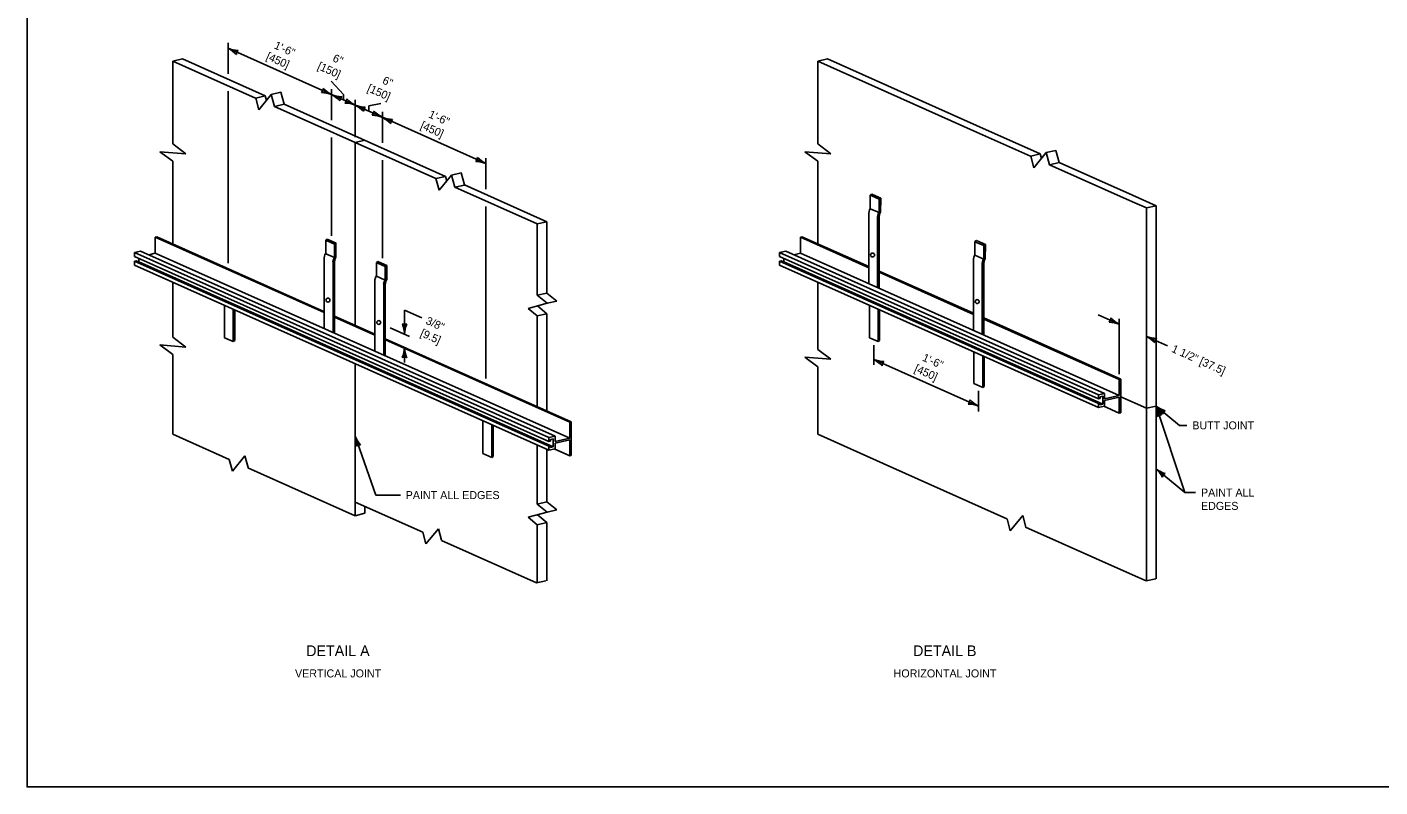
# Model space of a CAD drawing. Extents: x 49991.4 to 50021, y 49987.6 to 50011.4.
# Drawn here: x 49999.38 to 50009.53, y 49987.8 to 49993.5 of the extents above; entities that cross this region are included whole.
import ezdxf

# ---------------------------------------------------------------- set-up
doc = ezdxf.new("R2010")
doc.units = 0
for name, color, linetype in [('Level 1', 7, 'Continuous'), ('Level 2', 7, 'Continuous'), ('Level 3', 7, 'Continuous'), ('Level 6', 7, 'Continuous')]:
    doc.layers.add(name, color=color, linetype=linetype)

msp = doc.modelspace()

# ---------------------------------------------------------------- linework, layer by layer
at = {"layer": 'Level 1'}
for p, q in [((50001.844, 49991.263), (50001.844, 49992.63)), ((50005.718, 49992.243), (50005.707, 49992.236)), ((50005.707, 49992.134), (50005.707, 49992.236)), ((50005.718, 49992.231), (50005.707, 49992.236)), ((50005.785, 49992.213), (50005.718, 49992.243)), ((50005.774, 49992.206), (50005.718, 49992.231)), ((50005.773, 49992.105), (50005.774, 49992.206)), ((50005.785, 49992.213), (50005.774, 49992.206)), ((50005.784, 49992.106), (50005.785, 49992.213)), ((50007.85, 49989.36), (50007.85, 49992.157)), ((50005.695, 49991.572), (50005.696, 49992.102)), ((50005.773, 49992.105), (50005.707, 49992.134)), ((50005.762, 49991.543), (50005.762, 49992.073)), ((50005.773, 49991.538), (50005.773, 49992.074)), ((50007.778, 49989.343), (50007.778, 49992.14)), ((50000.345, 49991.92), (50000.357, 49991.923)), ((50000.345, 49991.8), (50000.345, 49991.92)), ((50001.611, 49991.355), (50000.345, 49991.92)), ((50001.61, 49991.364), (50000.357, 49991.923)), ((50001.634, 49991.906), (50001.623, 49991.898)), ((50001.623, 49991.797), (50001.623, 49991.898)), ((50001.634, 49991.893), (50001.623, 49991.898)), ((50001.701, 49991.876), (50001.634, 49991.906)), ((50001.689, 49991.868), (50001.634, 49991.893)), ((50001.701, 49991.876), (50001.689, 49991.868)), ((50001.689, 49991.768), (50001.689, 49991.868)), ((50001.7, 49991.768), (50001.7, 49991.876)), ((50005.183, 49991.921), (50005.194, 49991.924)), ((50005.183, 49991.801), (50005.183, 49991.921)), ((50005.695, 49991.692), (50005.183, 49991.921)), ((50005.695, 49991.7), (50005.194, 49991.924)), ((50006.503, 49991.895), (50006.492, 49991.888)), ((50006.492, 49991.786), (50006.492, 49991.888)), ((50006.503, 49991.882), (50006.492, 49991.888)), ((50006.57, 49991.865), (50006.503, 49991.895)), ((50006.559, 49991.858), (50006.503, 49991.882)), ((50006.558, 49991.757), (50006.559, 49991.858)), ((50006.57, 49991.865), (50006.559, 49991.858)), ((50006.569, 49991.757), (50006.57, 49991.865)), ((50000.189, 49991.806), (50000.235, 49991.817)), ((50000.189, 49991.806), (50000.189, 49991.776)), ((50003.297, 49990.419), (50000.189, 49991.806)), ((50003.297, 49990.389), (50000.189, 49991.776)), ((50000.221, 49991.736), (50000.221, 49991.762)), ((50003.343, 49990.43), (50000.235, 49991.817)), ((50000.345, 49991.8), (50000.297, 49991.789)), ((50003.453, 49990.414), (50000.345, 49991.8)), ((50001.611, 49991.236), (50001.611, 49991.765)), ((50001.689, 49991.768), (50001.623, 49991.797)), ((50005.027, 49991.806), (50005.073, 49991.817)), ((50007.418, 49990.739), (50005.027, 49991.806)), ((50005.027, 49991.806), (50005.027, 49991.777)), ((50007.418, 49990.709), (50005.027, 49991.776)), ((50005.059, 49991.737), (50005.059, 49991.762)), ((50007.464, 49990.75), (50005.073, 49991.817)), ((50005.183, 49991.801), (50005.135, 49991.789)), ((50007.574, 49990.734), (50005.183, 49991.801)), ((50006.48, 49991.222), (50006.481, 49991.754)), ((50006.558, 49991.757), (50006.492, 49991.786)), ((50000.189, 49991.741), (50000.201, 49991.743)), ((50003.297, 49990.354), (50000.189, 49991.741)), ((50000.189, 49991.741), (50000.189, 49991.711)), ((50003.297, 49990.324), (50000.189, 49991.711)), ((50003.308, 49990.356), (50000.201, 49991.743)), ((50000.221, 49991.736), (50000.219, 49991.735)), ((50003.328, 49990.35), (50000.221, 49991.736)), ((50001.678, 49991.206), (50001.678, 49991.735)), ((50001.689, 49991.201), (50001.689, 49991.736)), ((50002.015, 49991.738), (50002.003, 49991.73)), ((50002.003, 49991.628), (50002.003, 49991.73)), ((50002.015, 49991.725), (50002.003, 49991.73)), ((50002.081, 49991.708), (50002.015, 49991.738)), ((50002.07, 49991.7), (50002.015, 49991.725)), ((50002.069, 49991.599), (50002.07, 49991.7)), ((50002.081, 49991.708), (50002.07, 49991.7)), ((50002.081, 49991.6), (50002.081, 49991.708)), ((50005.027, 49991.741), (50005.039, 49991.744)), ((50007.418, 49990.674), (50005.027, 49991.741)), ((50005.027, 49991.741), (50005.027, 49991.711)), ((50007.418, 49990.644), (50005.027, 49991.711)), ((50007.43, 49990.676), (50005.039, 49991.744)), ((50005.056, 49991.736), (50005.059, 49991.737)), ((50007.45, 49990.67), (50005.059, 49991.737)), ((50006.48, 49991.35), (50005.773, 49991.665)), ((50006.48, 49991.342), (50005.773, 49991.658)), ((50006.547, 49991.192), (50006.547, 49991.725)), ((50006.558, 49991.187), (50006.558, 49991.725)), ((50001.992, 49991.066), (50001.992, 49991.596)), ((50002.069, 49991.599), (50002.003, 49991.628)), ((50002.058, 49991.036), (50002.058, 49991.567)), ((50002.069, 49991.031), (50002.069, 49991.568)), ((50000.863, 49991.41), (50000.863, 49991.167)), ((50000.929, 49991.38), (50000.929, 49991.138)), ((50000.941, 49991.375), (50000.941, 49991.145)), ((50005.7, 49991.411), (50005.7, 49991.167)), ((50005.766, 49991.381), (50005.766, 49991.138)), ((50005.777, 49991.376), (50005.777, 49991.145)), ((50001.991, 49991.194), (50001.689, 49991.329)), ((50001.992, 49991.185), (50001.689, 49991.321)), ((50007.586, 49990.856), (50006.558, 49991.315)), ((50007.574, 49990.853), (50006.558, 49991.307)), ((50000.929, 49991.138), (50000.863, 49991.167)), ((50000.941, 49991.145), (50000.929, 49991.138)), ((50003.464, 49990.536), (50002.07, 49991.158)), ((50003.453, 49990.533), (50002.071, 49991.15)), ((50005.766, 49991.138), (50005.7, 49991.167)), ((50005.777, 49991.145), (50005.766, 49991.138)), ((50006.484, 49991.061), (50006.484, 49990.823)), ((50001.844, 49989.832), (50001.844, 49990.972)), ((50006.551, 49991.031), (50006.551, 49990.794)), ((50006.562, 49991.026), (50006.562, 49990.801)), ((50007.574, 49990.853), (50007.586, 49990.856)), ((50007.574, 49990.734), (50007.574, 49990.853)), ((50007.586, 49990.699), (50007.586, 49990.856)), ((50007.586, 49990.604), (50007.586, 49990.856)), ((50006.551, 49990.794), (50006.484, 49990.823)), ((50006.562, 49990.801), (50006.551, 49990.794)), ((50007.418, 49990.739), (50007.464, 49990.75)), ((50007.418, 49990.739), (50007.418, 49990.709)), ((50007.464, 49990.708), (50007.464, 49990.75)), ((50007.418, 49990.709), (50007.43, 49990.712)), ((50007.418, 49990.674), (50007.43, 49990.676)), ((50007.418, 49990.674), (50007.418, 49990.644)), ((50007.418, 49990.644), (50007.464, 49990.655)), ((50007.43, 49990.724), (50007.45, 49990.728)), ((50007.43, 49990.724), (50007.43, 49990.712)), ((50007.43, 49990.676), (50007.43, 49990.665)), ((50007.43, 49990.665), (50007.45, 49990.67)), ((50007.45, 49990.67), (50007.45, 49990.728)), ((50007.574, 49990.602), (50007.459, 49990.653)), ((50007.574, 49990.734), (50007.464, 49990.708)), ((50007.574, 49990.722), (50007.464, 49990.696)), ((50007.464, 49990.655), (50007.464, 49990.696)), ((50007.574, 49990.602), (50007.574, 49990.722)), ((50007.778, 49990.638), (50007.586, 49990.723)), ((50007.778, 49990.638), (50007.85, 49990.654)), ((50002.801, 49990.545), (50002.801, 49990.298)), ((50003.45, 49990.533), (50003.465, 49990.536)), ((50003.453, 49990.533), (50003.464, 49990.536)), ((50003.453, 49990.414), (50003.453, 49990.533)), ((50003.464, 49990.284), (50003.464, 49990.536)), ((50007.574, 49990.602), (50007.586, 49990.604)), ((50002.868, 49990.515), (50002.868, 49990.269)), ((50002.879, 49990.51), (50002.879, 49990.276)), ((50003.297, 49990.419), (50003.343, 49990.43)), ((50003.297, 49990.419), (50003.297, 49990.389)), ((50003.297, 49990.389), (50003.308, 49990.392)), ((50003.297, 49990.354), (50003.308, 49990.356)), ((50003.297, 49990.354), (50003.297, 49990.324)), ((50003.297, 49990.324), (50003.343, 49990.335)), ((50003.308, 49990.403), (50003.328, 49990.408)), ((50003.308, 49990.403), (50003.308, 49990.392)), ((50003.308, 49990.356), (50003.308, 49990.345)), ((50003.308, 49990.345), (50003.328, 49990.35)), ((50003.328, 49990.35), (50003.328, 49990.408)), ((50003.453, 49990.282), (50003.337, 49990.333)), ((50003.343, 49990.388), (50003.343, 49990.43)), ((50003.453, 49990.414), (50003.343, 49990.388)), ((50003.453, 49990.402), (50003.343, 49990.376)), ((50003.343, 49990.335), (50003.343, 49990.376)), ((50003.453, 49990.282), (50003.453, 49990.402)), ((50002.868, 49990.269), (50002.801, 49990.298)), ((50002.879, 49990.276), (50002.868, 49990.269)), ((50003.453, 49990.282), (50003.464, 49990.284)), ((50001.916, 49989.851), (50001.916, 49989.903))]:
    msp.add_line(p, q, dxfattribs=at)
msp.add_lwpolyline([(49999.384, 49998.999), (50016.75, 49998.999), (50016.75, 49987.799), (49999.384, 49987.799)], close=True, dxfattribs=at)
for centre in [(50005.724, 49991.787), (50001.64, 49991.449), (50006.509, 49991.438), (50002.021, 49991.281)]:
    msp.add_circle(centre, 0.0147, dxfattribs=at)
for centre, start_param, end_param in [((50005.702, 49992.101), 0.015278, 1.570796), ((50005.768, 49992.072), 6.267677, 7.853982), ((50005.779, 49992.073), 6.255637, 7.853982), ((50001.618, 49991.764), 0, 1.570796), ((50001.684, 49991.734), 0, 1.570796), ((50001.695, 49991.735), 0, 1.570796), ((50006.487, 49991.753), 6.276621, 7.853982), ((50006.553, 49991.724), 6.261574, 7.853982), ((50006.564, 49991.724), 6.249472, 7.853982), ((50001.998, 49991.595), 6.271013, 7.853982), ((50002.064, 49991.566), 6.256054, 7.853982), ((50002.076, 49991.567), 6.24387, 7.853982)]:
    msp.add_ellipse(centre, major_axis=(0.0049, 0.033), ratio=0.190283, start_param=start_param, end_param=end_param, dxfattribs=at)
at = {"layer": 'Level 3'}
for p, q in [((50000.891, 49993.145), (50000.891, 49993.377)), ((50001.667, 49992.99), (50000.891, 49993.337)), ((50001.756, 49992.99), (50001.664, 49993.091)), ((50000.891, 49991.725), (50000.891, 49993.016)), ((50001.667, 49992.798), (50001.667, 49993.03)), ((50001.844, 49992.911), (50001.667, 49992.99)), ((50001.756, 49992.95), (50001.756, 49992.99)), ((50001.844, 49992.67), (50001.844, 49992.951)), ((50002.048, 49992.82), (50001.844, 49992.911)), ((50001.946, 49992.905), (50002.037, 49992.924)), ((50001.946, 49992.865), (50001.946, 49992.905)), ((50002.048, 49992.628), (50002.048, 49992.86)), ((50002.824, 49992.473), (50002.048, 49992.82)), ((50001.667, 49991.931), (50001.667, 49992.669)), ((50002.048, 49991.763), (50002.048, 49992.499)), ((50002.824, 49992.281), (50002.824, 49992.513)), ((50002.824, 49990.862), (50002.824, 49992.152)), ((50002.214, 49991.194), (50002.214, 49991.374)), ((50002.344, 49991.316), (50002.214, 49991.374)), ((50007.574, 49991.268), (50007.416, 49991.339)), ((50007.574, 49990.893), (50007.574, 49991.308)), ((50002.251, 49991.177), (50002.106, 49991.242)), ((50007.937, 49991.107), (50007.778, 49991.177)), ((50002.214, 49990.982), (50002.214, 49991.094)), ((50005.733, 49990.964), (50005.733, 49991.112)), ((50006.518, 49990.655), (50005.733, 49991.004)), ((50006.518, 49990.615), (50006.518, 49990.768)), ((50007.85, 49990.654), (50008.025, 49990.51)), ((50007.85, 49990.654), (50008.065, 49990.006)), ((50008.025, 49990.51), (50008.082, 49990.51)), ((50001.998, 49989.987), (50001.844, 49990.43)), ((50008.065, 49990.006), (50007.85, 49990.184)), ((50001.998, 49989.987), (50002.183, 49989.987)), ((50008.065, 49990.006), (50008.147, 49990.006))]:
    msp.add_line(p, q, dxfattribs=at)
for centre, radius, start, end in [((50000.792, 49993.138), 0.222, 43.3799, 63.5634), ((50000.975, 49993.554), 0.233, 248.7512, 268.001), ((50001.008, 49993.285), 0.0548, 138.0627, 173.785), ((50001.55, 49993.042), 0.0548, 318.0627, 353.785), ((50001.583, 49992.773), 0.233, 68.7512, 88.001), ((50001.766, 49993.189), 0.222, 223.3799, 243.5634), ((50001.568, 49992.791), 0.222, 43.3799, 63.5634), ((50001.752, 49993.207), 0.233, 248.7512, 268.001), ((50001.784, 49992.938), 0.0548, 138.0627, 173.785), ((50001.727, 49992.963), 0.0548, 318.0627, 353.785), ((50001.759, 49992.694), 0.233, 68.7512, 88.001), ((50001.943, 49993.11), 0.222, 223.3799, 243.5634), ((50001.745, 49992.712), 0.222, 43.3799, 63.5634), ((50001.928, 49993.128), 0.233, 248.7512, 268.001), ((50001.961, 49992.859), 0.0548, 138.0627, 173.785), ((50001.931, 49992.872), 0.0548, 318.0627, 353.785), ((50002.147, 49993.019), 0.222, 223.3799, 243.5634), ((50001.964, 49992.602), 0.233, 68.7512, 88.001), ((50001.949, 49992.62), 0.222, 43.3799, 63.5634), ((50002.133, 49993.037), 0.233, 248.7512, 268.001), ((50002.165, 49992.767), 0.0548, 138.0627, 173.785), ((50002.707, 49992.525), 0.0548, 318.0636, 353.7859), ((50002.74, 49992.256), 0.233, 68.7521, 88.0019), ((50002.923, 49992.672), 0.222, 223.3808, 243.5643), ((50002.214, 49991.322), 0.0548, 252.1388, 287.8612), ((50001.982, 49991.182), 0.233, 2.8273, 22.0772), ((50002.436, 49991.184), 0.222, 157.456, 177.6395), ((50007.457, 49991.321), 0.0548, 318.0614, 353.7837), ((50007.49, 49991.051), 0.233, 68.7499, 87.9997), ((50007.673, 49991.467), 0.222, 223.3786, 243.5621), ((50007.679, 49990.978), 0.222, 43.3567, 63.5402), ((50007.863, 49991.394), 0.233, 248.728, 267.9779), ((50007.895, 49991.125), 0.0548, 138.0395, 173.7619), ((50001.992, 49991.103), 0.222, 337.456, 357.6395), ((50002.447, 49991.105), 0.233, 182.8273, 202.0772), ((50002.214, 49990.966), 0.0548, 72.1388, 107.8612), ((50005.634, 49990.804), 0.222, 43.3725, 63.556), ((50005.817, 49991.221), 0.233, 248.7438, 267.9937), ((50005.85, 49990.951), 0.0548, 138.0553, 173.7777), ((50006.4, 49990.707), 0.0548, 318.0553, 353.7777), ((50006.433, 49990.437), 0.233, 68.7438, 87.9937), ((50006.617, 49990.854), 0.222, 223.3725, 243.556), ((50008.065, 49990.743), 0.233, 202.35, 221.5999), ((50007.703, 49990.487), 0.222, 28.596, 48.7796), ((50007.987, 49990.842), 0.233, 233.9673, 253.2172), ((50007.637, 49990.588), 0.222, 356.9787, 17.1622), ((50007.892, 49990.533), 0.0548, 91.6615, 127.3839), ((50007.949, 49990.574), 0.0548, 123.2789, 159.0012), ((50001.631, 49990.366), 0.222, 356.5842, 16.7677), ((50002.06, 49990.517), 0.233, 201.9555, 221.2053), ((50001.886, 49990.309), 0.0548, 91.267, 126.9894), ((50007.701, 49990.019), 0.222, 27.7606, 47.9441), ((50007.989, 49990.37), 0.233, 233.1319, 252.3818), ((50007.948, 49990.102), 0.0548, 122.4434, 158.1658)]:
    msp.add_arc(centre, radius, start, end, dxfattribs=at)
at = {"layer": 'Level 6'}
for p, q in [((50000.477, 49993.241), (50000.549, 49993.257)), ((50001.097, 49992.964), (50000.477, 49993.241)), ((50000.477, 49992.62), (50000.477, 49993.241)), ((50001.169, 49992.981), (50000.549, 49993.257)), ((50005.314, 49993.241), (50005.386, 49993.257)), ((50005.933, 49992.964), (50005.314, 49993.241)), ((50005.314, 49992.62), (50005.314, 49993.241)), ((50006.006, 49992.981), (50005.386, 49993.257)), ((50001.098, 49992.964), (50001.17, 49992.981)), ((50001.122, 49992.876), (50001.215, 49992.99)), ((50001.179, 49992.946), (50001.17, 49992.981)), ((50001.215, 49992.99), (50001.287, 49993.007)), ((50001.215, 49992.99), (50001.239, 49992.9)), ((50001.312, 49992.917), (50001.287, 49993.007)), ((50006.504, 49992.758), (50006.006, 49992.981)), ((50001.098, 49992.964), (50001.122, 49992.876)), ((50001.239, 49992.9), (50001.312, 49992.917)), ((50002.449, 49992.36), (50001.239, 49992.9)), ((50002.521, 49992.377), (50001.312, 49992.917)), ((50006.504, 49992.709), (50005.933, 49992.964)), ((50006.981, 49992.545), (50006.504, 49992.758)), ((50006.909, 49992.528), (50006.504, 49992.709)), ((50000.38, 49992.562), (50000.477, 49992.49)), ((50000.38, 49992.562), (50000.574, 49992.547)), ((50000.477, 49992.62), (50000.574, 49992.547)), ((50001.844, 49992.63), (50001.916, 49992.647)), ((50005.217, 49992.562), (50005.314, 49992.49)), ((50005.217, 49992.562), (50005.411, 49992.547)), ((50005.314, 49992.62), (50005.411, 49992.547)), ((50007.027, 49992.555), (50007.099, 49992.572)), ((50007.124, 49992.481), (50007.099, 49992.572)), ((50000.477, 49991.869), (50000.477, 49992.49)), ((50005.314, 49991.869), (50005.314, 49992.49)), ((50006.91, 49992.529), (50006.982, 49992.546)), ((50006.934, 49992.441), (50006.91, 49992.529)), ((50007.027, 49992.555), (50006.934, 49992.441)), ((50006.992, 49992.512), (50006.982, 49992.546)), ((50007.052, 49992.464), (50007.027, 49992.555)), ((50007.052, 49992.464), (50007.124, 49992.481)), ((50007.674, 49992.186), (50007.052, 49992.464)), ((50007.674, 49992.235), (50007.124, 49992.481)), ((50002.45, 49992.36), (50002.522, 49992.377)), ((50002.474, 49992.273), (50002.45, 49992.36)), ((50002.567, 49992.387), (50002.474, 49992.273)), ((50002.532, 49992.343), (50002.522, 49992.377)), ((50002.567, 49992.387), (50002.64, 49992.404)), ((50002.592, 49992.296), (50002.567, 49992.387)), ((50002.664, 49992.313), (50002.64, 49992.404)), ((50002.592, 49992.296), (50002.664, 49992.312)), ((50003.21, 49992.02), (50002.592, 49992.296)), ((50003.282, 49992.037), (50002.664, 49992.313)), ((50007.85, 49992.157), (50007.674, 49992.235)), ((50007.778, 49992.14), (50007.674, 49992.186)), ((50007.778, 49992.14), (50007.85, 49992.157)), ((50003.21, 49992.02), (50003.282, 49992.037)), ((50003.21, 49991.485), (50003.21, 49992.02)), ((50003.282, 49991.501), (50003.282, 49992.037)), ((50000.477, 49991.17), (50000.477, 49991.582)), ((50005.314, 49991.078), (50005.314, 49991.584)), ((50003.21, 49991.485), (50003.282, 49991.501)), ((50003.21, 49991.485), (50003.283, 49991.425)), ((50003.282, 49991.501), (50003.356, 49991.442)), ((50003.283, 49991.425), (50003.141, 49991.386)), ((50003.141, 49991.386), (50003.21, 49991.33)), ((50003.21, 49991.33), (50003.282, 49991.346)), ((50003.211, 49991.405), (50003.282, 49991.346)), ((50003.282, 49990.619), (50003.282, 49991.346)), ((50003.283, 49991.425), (50003.356, 49991.442)), ((50003.21, 49990.647), (50003.21, 49991.33)), ((50000.477, 49991.17), (50000.574, 49991.097)), ((50000.38, 49991.113), (50000.477, 49991.04)), ((50000.38, 49991.113), (50000.574, 49991.097)), ((50000.477, 49990.443), (50000.477, 49991.04)), ((50005.314, 49991.078), (50005.411, 49991.006)), ((50005.217, 49991.021), (50005.314, 49990.949)), ((50005.217, 49991.021), (50005.411, 49991.006)), ((50005.314, 49990.443), (50005.314, 49990.949)), ((50000.9, 49990.254), (50000.477, 49990.443)), ((50005.877, 49990.192), (50005.314, 49990.443)), ((50003.21, 49989.919), (50003.21, 49990.362)), ((50003.282, 49989.936), (50003.282, 49990.33)), ((50000.923, 49990.167), (50000.9, 49990.254)), ((50001.017, 49990.281), (50000.923, 49990.167)), ((50001.041, 49990.193), (50001.017, 49990.281)), ((50001.844, 49989.832), (50001.04, 49990.192)), ((50006.732, 49989.81), (50005.877, 49990.192)), ((50002.351, 49989.709), (50001.844, 49989.935)), ((50003.21, 49989.919), (50003.282, 49989.936)), ((50003.282, 49989.936), (50003.356, 49989.876)), ((50001.844, 49989.832), (50001.916, 49989.851)), ((50003.283, 49989.859), (50003.141, 49989.821)), ((50003.21, 49989.919), (50003.283, 49989.859)), ((50003.211, 49989.84), (50003.282, 49989.781)), ((50003.283, 49989.859), (50003.356, 49989.876)), ((50006.85, 49989.834), (50006.757, 49989.72)), ((50006.874, 49989.747), (50006.85, 49989.834)), ((50002.375, 49989.621), (50002.468, 49989.735)), ((50002.468, 49989.735), (50002.492, 49989.648)), ((50003.141, 49989.821), (50003.21, 49989.764)), ((50003.21, 49989.764), (50003.282, 49989.781)), ((50003.21, 49989.331), (50003.21, 49989.764)), ((50003.282, 49989.345), (50003.282, 49989.781)), ((50006.757, 49989.72), (50006.733, 49989.808)), ((50007.674, 49989.388), (50006.872, 49989.747)), ((50002.351, 49989.709), (50002.375, 49989.621)), ((50003.203, 49989.328), (50002.491, 49989.646)), ((50003.203, 49989.328), (50003.275, 49989.345)), ((50007.776, 49989.343), (50007.674, 49989.388)), ((50007.776, 49989.343), (50007.848, 49989.36))]:
    msp.add_line(p, q, dxfattribs=at)

# ---------------------------------------------------------------- texts
at = {"layer": 'Level 2'}
for s, p in [('1\'-6"', (50001.231, 49993.338)), ('[450]', (50001.171, 49993.256)), ('6"', (50001.67, 49993.242)), ('[150]', (50001.556, 49993.183)), ('[150]', (50001.929, 49993.017)), ('6"', (50002.043, 49993.075)), ('1\'-6"', (50002.389, 49992.821)), ('[450]', (50002.328, 49992.738)), ('3/8"', (50002.368, 49991.273)), ('[9.5]', (50002.327, 49991.181)), ('1\'-6"', (50006.092, 49990.997)), ('1 1/2" [37.5]', (50007.961, 49991.063)), ('[450]', (50006.032, 49990.915))]:
    msp.add_text(s, height=0.06, rotation=335.924, dxfattribs=at).set_placement(p)
for s, height, p in [('BUTT JOINT', 0.06, (50008.122, 49990.48)), ('PAINT ALL', 0.06, (50008.187, 49989.976)), ('PAINT ALL EDGES', 0.06, (50002.223, 49989.957)), ('EDGES', 0.06, (50008.187, 49989.876)), ('DETAIL A', 0.08, (50001.477, 49988.78)), ('DETAIL B', 0.08, (50006.028, 49988.78)), ('VERTICAL JOINT', 0.06, (50001.393, 49988.62)), ('HORIZONTAL JOINT', 0.06, (50005.882, 49988.62))]:
    msp.add_text(s, height=height, dxfattribs=at).set_placement(p)

doc.saveas('drawing.dxf')
